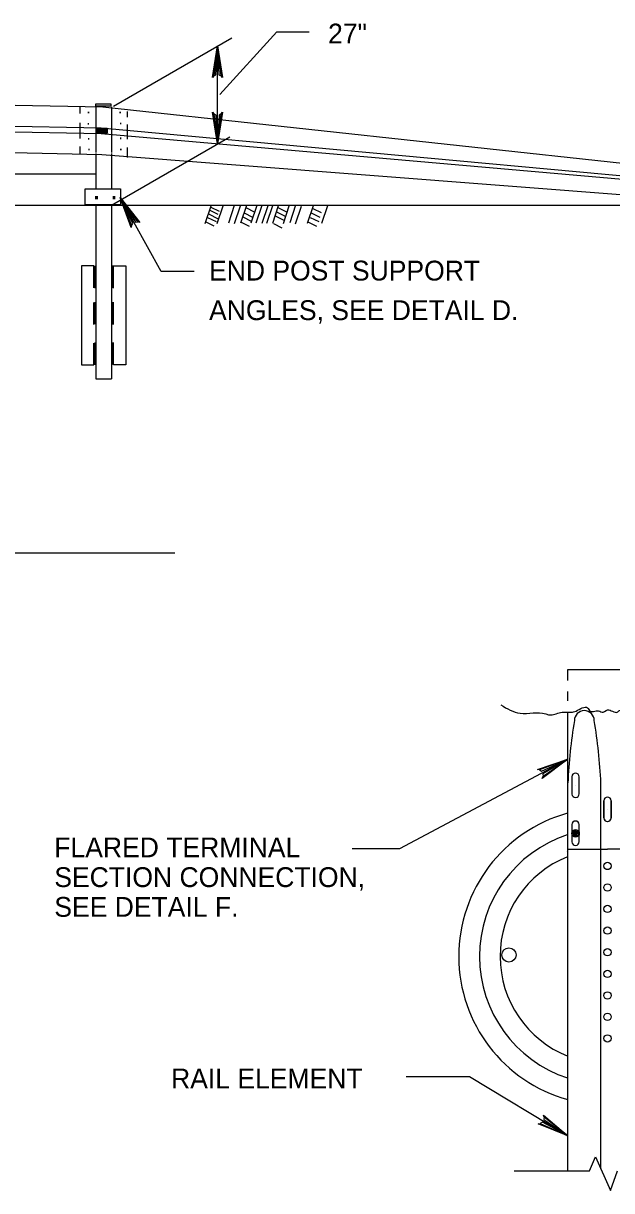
# Model space of a CAD drawing. Extents: x 637628 to 640188, y 298266 to 300751.
# Drawn here: x 638881.6 to 638970.6, y 298525 to 298701.7 of the extents above; entities that cross this region are included whole.
import ezdxf

# ---------------------------------------------------------------- set-up
doc = ezdxf.new("R2010")
doc.units = 0
for name, color, linetype in [('1', 7, 'Continuous'), ('2', 7, 'Continuous'), ('3', 7, 'Continuous')]:
    doc.layers.add(name, color=color, linetype=linetype)

msp = doc.modelspace()

# ---------------------------------------------------------------- linework, layer by layer
at = {"layer": '1'}
msp.add_line((638804.11, 298678.86), (638892.56, 298678.86), dxfattribs=at)
msp.add_circle((638955.1, 298560.66), 1.08, dxfattribs=at)
at = {"layer": '2'}
for p, q in [((638895.25, 298689.13), (638913.15, 298699.47)), ((638911.34, 298690.89), (638919.99, 298700.38)), ((638919.99, 298700.38), (638924.88, 298700.38)), ((638911, 298683.41), (638911, 298698.23)), ((638803.1, 298690.89), (638893.62, 298689)), ((638890.17, 298689), (638890.17, 298687.99)), ((638892.56, 298689), (638892.56, 298682.13)), ((638893.62, 298689), (639030.47, 298674.15)), ((638894.95, 298689), (638894.95, 298682.13)), ((638897.34, 298688.33), (638897.34, 298687.47)), ((638802.53, 298687.73), (638893.38, 298685.84)), ((638802.72, 298686.87), (638893.39, 298684.98)), ((638890.17, 298686.6), (638890.17, 298684.22)), ((638893.38, 298685.84), (639020.26, 298674.15)), ((638893.39, 298684.98), (639016.92, 298674.15)), ((638897.34, 298686.34), (638897.34, 298684.13)), ((638802.93, 298683.71), (638893.5, 298681.82)), ((638890.17, 298683), (638890.17, 298681.81)), ((638894.96, 298674.15), (638912.86, 298684.49)), ((638897.34, 298682.87), (638897.34, 298681.37)), ((638892.56, 298681.95), (638892.56, 298676.64)), ((638893.5, 298681.82), (638992.56, 298674.15)), ((638894.95, 298681.95), (638894.95, 298676.57)), ((638525.21, 298674.15), (638992.56, 298674.15)), ((638892.56, 298674.15), (638892.56, 298647.85)), ((638894.95, 298674.08), (638894.95, 298647.85)), ((638913.54, 298674.09), (638912.65, 298671.41)), ((638915.39, 298674.09), (638914.5, 298671.41)), ((638916.95, 298674.09), (638916.06, 298671.41)), ((638917.71, 298674.09), (638916.81, 298671.41)), ((638918.6, 298674.04), (638917.71, 298671.36)), ((638919.31, 298674.04), (638918.42, 298671.36)), ((638920.19, 298674.04), (638919.3, 298671.36)), ((638922.82, 298674.15), (638921.92, 298671.47)), ((638925.46, 298674.04), (638924.56, 298671.36)), ((638927.63, 298674.04), (638926.73, 298671.36)), ((638909.97, 298674), (638909.07, 298671.32)), ((638909.5, 298672.29), (638910.79, 298671.65)), ((638909.61, 298672.81), (638911.12, 298672.06)), ((638909.82, 298673.38), (638911.07, 298672.75)), ((638909.97, 298673.85), (638911.23, 298673.22)), ((638911.78, 298674), (638910.89, 298671.32)), ((638914.41, 298673.98), (638913.51, 298671.3)), ((638914.82, 298672.35), (638916.11, 298671.7)), ((638915.02, 298672.97), (638916.31, 298672.32)), ((638915.29, 298673.79), (638916.57, 298673.15)), ((638919.72, 298672.5), (638921.01, 298671.86)), ((638919.93, 298673.12), (638921.22, 298672.47)), ((638920.14, 298673.79), (638921.42, 298673.15)), ((638921.8, 298674), (638920.91, 298671.32)), ((638923.66, 298673.94), (638922.76, 298671.26)), ((638925.04, 298672.29), (638926.33, 298671.65)), ((638925.19, 298672.97), (638926.48, 298672.32)), ((638925.4, 298673.64), (638926.69, 298673)), ((638909.24, 298671.62), (638910.42, 298671.03)), ((638914.5, 298671.62), (638915.79, 298670.98)), ((638919.46, 298671.36), (638920.75, 298670.71)), ((638924.67, 298671.62), (638925.96, 298670.98)), ((638892.44, 298664.94), (638892.44, 298661.57)), ((638895.11, 298664.99), (638895.11, 298661.62)), ((638892.42, 298659.46), (638892.42, 298656.1)), ((638895.06, 298659.44), (638895.06, 298656.07)), ((638892.44, 298653.34), (638892.44, 298649.97)), ((638895.13, 298653.36), (638895.13, 298650)), ((638964.01, 298603.88), (638976.01, 298603.88)), ((638964.01, 298602.17), (638964.01, 298603.88)), ((638964.01, 298599.13), (638964.01, 298600.53)), ((638964.01, 298527.99), (638964.01, 298597.4)), ((638968.51, 298592.63), (638968.51, 298592.63)), ((638964.62, 298587.63), (638964.62, 298585)), ((638965.72, 298585.04), (638965.72, 298587.63)), ((638965.17, 298586.31), (638965.17, 298586.31)), ((638965.17, 298586.31), (638965.17, 298586.31)), ((638969.01, 298528.27), (638969.01, 298586.69)), ((638969.46, 298581.42), (638969.46, 298584)), ((638969.46, 298584), (638969.46, 298581.38)), ((638970.57, 298584), (638970.57, 298581.38)), ((638970.57, 298581.42), (638970.57, 298584)), ((638970.01, 298582.69), (638970.01, 298582.69)), ((638970.01, 298582.69), (638970.01, 298582.69)), ((638964.62, 298580.38), (638964.62, 298577.75)), ((638965.54, 298579.15), (638964.7, 298578.99)), ((638965.11, 298578.6), (638964.7, 298579.12)), ((638964.7, 298579.12), (638965.41, 298578.6)), ((638964.7, 298578.99), (638965.64, 298579.02)), ((638965.4, 298579.41), (638964.74, 298579.19)), ((638964.74, 298579.19), (638965.54, 298579.15)), ((638965.64, 298579.02), (638964.81, 298578.77)), ((638964.81, 298578.77), (638965.58, 298578.78)), ((638964.86, 298579.41), (638965.4, 298579.41)), ((638965.41, 298578.6), (638965.08, 298579.53)), ((638965.08, 298579.53), (638965.65, 298578.93)), ((638965.58, 298578.78), (638965.11, 298578.6)), ((638965.17, 298579.06), (638965.17, 298579.06)), ((638965.17, 298579.06), (638965.17, 298579.06)), ((638965.18, 298579.06), (638965.18, 298579.06)), ((638965.65, 298578.93), (638965.48, 298579.48)), ((638965.72, 298577.79), (638965.72, 298580.38)), ((638963.77, 298576.26), (638963.77, 298576.26)), ((638964.01, 298576.69), (638970.01, 298576.69)), ((638976.01, 298576.69), (638970.01, 298576.69)), ((638939.57, 298542.26), (638949.11, 298542.26)), ((638955.89, 298527.99), (638967.29, 298527.99))]:
    msp.add_line(p, q, dxfattribs=at)
for points in [[(638910.43, 298693.69), (638910.76, 298693.86), (638911, 298698.23), (638910.43, 298693.69), (638910.23, 298693.45), (638911, 298698.23), (638911.22, 298693.86), (638911.54, 298693.7), (638911, 298698.23), (638911.76, 298693.45), (638911.54, 298693.7)], [(638911.57, 298687.95), (638911.24, 298687.78), (638911, 298683.41), (638911.57, 298687.95), (638911.77, 298688.19), (638911, 298683.41), (638910.79, 298687.78), (638910.46, 298687.94), (638911, 298683.41), (638910.24, 298688.19), (638910.46, 298687.94)], [(638907.49, 298664.08), (638902.49, 298664.08), (638896.28, 298675.3)], [(638897.98, 298671.05), (638898.19, 298671.35), (638896.28, 298675.3), (638897.98, 298671.05), (638897.92, 298670.75), (638896.28, 298675.3), (638898.59, 298671.58), (638898.95, 298671.6), (638896.28, 298675.3), (638899.26, 298671.49), (638898.95, 298671.6)], [(638892.28, 298661.62), (638892.28, 298664.96), (638890.42, 298664.96), (638890.42, 298649.96), (638892.28, 298649.96), (638892.28, 298653.25)], [(638895.27, 298661.59), (638895.27, 298664.97), (638897.13, 298664.97), (638897.13, 298649.97), (638895.27, 298649.97), (638895.27, 298653.34)], [(638892.28, 298656.09), (638892.28, 298659.41)], [(638895.27, 298656.06), (638895.27, 298659.44)], [(638931.39, 298576.76), (638938.57, 298576.76), (638964.01, 298590.29)], [(638959.73, 298588.66), (638960.04, 298588.45), (638964.01, 298590.29), (638959.73, 298588.66), (638959.44, 298588.73), (638964.01, 298590.29), (638960.25, 298588.05), (638960.27, 298587.69), (638964.01, 298590.29), (638960.15, 298587.38), (638960.27, 298587.69)], [(638949.11, 298542.26), (638964.01, 298533.29)], [(638960.41, 298536.12), (638960.39, 298535.76), (638964.01, 298533.29), (638960.41, 298536.12), (638960.31, 298536.42), (638964.01, 298533.29), (638960.16, 298535.36), (638959.85, 298535.17), (638964.01, 298533.29), (638959.53, 298535.11), (638959.85, 298535.17)], [(638967.29, 298527.99), (638968.21, 298530.09), (638970.46, 298524.98), (638971.51, 298527.99)]]:
    msp.add_lwpolyline(points, dxfattribs=at)
for points in [[(638892.6, 298689.11), (638892.6, 298689.49), (638894.85, 298689.49), (638894.85, 298689.11)], [(638892.84, 298685.01), (638892.84, 298685.79), (638894.31, 298685.79), (638894.31, 298685.01)], [(638892.87, 298685.03), (638892.87, 298685.77), (638894.27, 298685.77), (638894.27, 298685.03)], [(638892.9, 298685.05), (638892.9, 298685.75), (638894.22, 298685.75), (638894.22, 298685.05)], [(638892.92, 298685.07), (638892.92, 298685.74), (638894.18, 298685.74), (638894.18, 298685.07)], [(638892.95, 298685.09), (638892.95, 298685.72), (638894.14, 298685.72), (638894.14, 298685.09)], [(638892.97, 298685.11), (638892.97, 298685.71), (638894.11, 298685.71), (638894.11, 298685.11)], [(638892.99, 298685.12), (638892.99, 298685.7), (638894.07, 298685.7), (638894.07, 298685.12)], [(638893.01, 298685.14), (638893.01, 298685.68), (638894.04, 298685.68), (638894.04, 298685.14)], [(638893.03, 298685.15), (638893.03, 298685.67), (638894.01, 298685.67), (638894.01, 298685.15)], [(638893.05, 298685.17), (638893.05, 298685.66), (638893.98, 298685.66), (638893.98, 298685.17)], [(638893.08, 298685.18), (638893.08, 298685.64), (638893.96, 298685.64), (638893.96, 298685.18)], [(638893.1, 298685.19), (638893.1, 298685.63), (638893.94, 298685.63), (638893.94, 298685.19)], [(638893.12, 298685.2), (638893.12, 298685.62), (638893.92, 298685.62), (638893.92, 298685.2)], [(638893.15, 298685.21), (638893.15, 298685.61), (638893.9, 298685.61), (638893.9, 298685.21)], [(638893.17, 298685.22), (638893.17, 298685.6), (638893.88, 298685.6), (638893.88, 298685.22)], [(638893.19, 298685.22), (638893.19, 298685.59), (638893.87, 298685.59), (638893.87, 298685.22)], [(638893.21, 298685.23), (638893.21, 298685.58), (638893.85, 298685.58), (638893.85, 298685.23)], [(638893.22, 298685.24), (638893.22, 298685.57), (638893.84, 298685.57), (638893.84, 298685.24)], [(638893.24, 298685.25), (638893.24, 298685.56), (638893.83, 298685.56), (638893.83, 298685.25)], [(638893.26, 298685.25), (638893.26, 298685.55), (638893.81, 298685.55), (638893.81, 298685.25)], [(638893.27, 298685.26), (638893.27, 298685.54), (638893.8, 298685.54), (638893.8, 298685.26)], [(638893.28, 298685.27), (638893.28, 298685.53), (638893.79, 298685.53), (638893.79, 298685.27)], [(638893.3, 298685.27), (638893.3, 298685.53), (638893.78, 298685.53), (638893.78, 298685.27)], [(638893.31, 298685.28), (638893.31, 298685.52), (638893.77, 298685.52), (638893.77, 298685.28)], [(638893.32, 298685.29), (638893.32, 298685.51), (638893.75, 298685.51), (638893.75, 298685.29)], [(638893.33, 298685.29), (638893.33, 298685.51), (638893.74, 298685.51), (638893.74, 298685.29)], [(638893.35, 298685.3), (638893.35, 298685.5), (638893.73, 298685.5), (638893.73, 298685.3)], [(638893.36, 298685.3), (638893.36, 298685.5), (638893.73, 298685.5), (638893.73, 298685.3)], [(638893.37, 298685.3), (638893.37, 298685.49), (638893.72, 298685.49), (638893.72, 298685.3)], [(638893.38, 298685.31), (638893.38, 298685.49), (638893.71, 298685.49), (638893.71, 298685.31)], [(638893.38, 298685.31), (638893.38, 298685.48), (638893.7, 298685.48), (638893.7, 298685.31)], [(638893.39, 298685.32), (638893.39, 298685.47), (638893.69, 298685.47), (638893.69, 298685.32)], [(638893.4, 298685.32), (638893.4, 298685.47), (638893.69, 298685.47), (638893.69, 298685.32)], [(638893.41, 298685.32), (638893.41, 298685.47), (638893.68, 298685.47), (638893.68, 298685.32)], [(638893.42, 298685.33), (638893.42, 298685.46), (638893.68, 298685.46), (638893.68, 298685.33)], [(638896.31, 298676.62), (638896.31, 298674.19), (638890.98, 298674.19), (638890.98, 298676.62)]]:
    msp.add_lwpolyline(points, close=True, dxfattribs=at)
for centre, radius in [((638965.18, 298579.06), 0.569), ((638970.01, 298574.12), 0.553), ((638970.01, 298570.87), 0.553), ((638970.01, 298567.62), 0.553), ((638970.01, 298564.34), 0.553), ((638970.01, 298561.06), 0.553), ((638970.01, 298557.78), 0.553), ((638970.01, 298554.53), 0.553), ((638970.01, 298551.28), 0.553), ((638970.01, 298548.03), 0.553)]:
    msp.add_circle(centre, radius, dxfattribs=at)
for centre, radius, start, end in [((638966.51, 298596.13), 1.5, 0, 180), ((639045.86, 298582.8), 81.94, 170.6336, 177.279), ((638887.17, 298582.8), 81.94, 2.721, 9.3664), ((638965.17, 298587.62), 0.554, 0.6286, 178.7414), ((638965.17, 298585.04), 0.554, 183.1764, 1.2759), ((638970.01, 298583.99), 0.554, 1.2586, 179.3714), ((638970.01, 298583.99), 0.554, 0.6286, 178.7414), ((638970.01, 298560.44), 22.5, 105.6165, 254.5531), ((638965.17, 298580.37), 0.554, 0.6286, 178.7414), ((638970.01, 298581.41), 0.554, 178.7241, 356.8236), ((638970.01, 298581.41), 0.554, 183.1764, 1.2759), ((638970.01, 298560.44), 19.37, 108.2909, 251.8521), ((638965.17, 298577.79), 0.554, 183.1764, 1.2759), ((638970.01, 298560.44), 16.25, 111.8318, 248.3747)]:
    msp.add_arc(centre, radius, start, end, dxfattribs=at)
msp.add_spline([(638953.89, 298598.5), (638956.8, 298597.23), (638960.67, 298597.16), (638961.25, 298596.99), (638961.65, 298596.99), (638962.48, 298597.24), (638963.38, 298597.4), (638964.52, 298597.4), (638965.26, 298597.57), (638966.98, 298598.06), (638967.39, 298597.57), (638968.86, 298597.57), (638969.19, 298597.4), (638970.01, 298597.73), (638971.49, 298597.4), (638971.81, 298597.65), (638972.96, 298597.65), (638974.84, 298597.65), (638975.91, 298597.81), (638976.48, 298597.9), (638977.71, 298597.98), (638978.37, 298598.06), (638982.25, 298597.74), (638985.92, 298595.84)], degree=3, dxfattribs=at)
at = {"layer": '3'}
for p, q in [((638892.56, 298647.85), (638894.95, 298647.85)), ((638720.61, 298621.52), (638904.56, 298621.52))]:
    msp.add_line(p, q, dxfattribs=at)

# ---------------------------------------------------------------- texts
for s, height, p in [('27"', 3, (638927.73, 298698.61)), ('.', 1.72, (638891.15, 298688.03)), ('.', 1.72, (638895.95, 298688.03)), ('.', 1.72, (638891.14, 298686.32)), ('.', 1.72, (638896.01, 298686.35)), ('.', 1.72, (638891.17, 298684.04)), ('.', 1.72, (638896.01, 298684.11)), ('.', 1.72, (638891.22, 298682.44)), ('.', 1.72, (638896.04, 298682.44)), ('.', 3.44, (638892.03, 298675)), ('.', 3.44, (638894.69, 298675)), ('END POST SUPPORT', 3, (638909.72, 298662.73)), ('ANGLES, SEE DETAIL D.', 3, (638909.72, 298656.74)), ('FLARED TERMINAL', 3, (638886.3, 298575.43)), ('SECTION CONNECTION,', 3, (638886.3, 298570.93)), ('SEE DETAIL F.', 3, (638886.3, 298566.43)), ('RAIL ELEMENT', 3, (638903.97, 298540.46))]:
    msp.add_text(s, height=height, dxfattribs=at).set_placement(p)

doc.saveas('drawing.dxf')
